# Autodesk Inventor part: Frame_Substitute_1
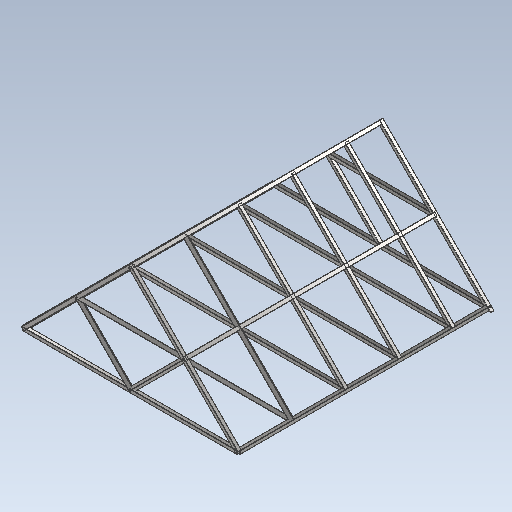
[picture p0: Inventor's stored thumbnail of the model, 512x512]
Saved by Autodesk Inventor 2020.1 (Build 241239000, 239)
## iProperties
Created: 2019-10
Part Number: Frame_Substitute_1
Material: Generic
Document SubType Name: Modeling
Designer: Synergysoft Dell02
Density: 1 g/cm^3
Appearance: Default
Author: Synergysoft Dell02
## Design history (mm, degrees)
derived "Frame.iam"
body "Solid1"
node "Frame 1572343187933.iam:1::ISO 100x100x4:1"
node "Frame 1572343187933.iam:1::ISO 100x100x4:2"
body "Solid2"
node "Frame 1572343187933.iam:1::ISO 100x100x4:3"
body "Solid3"
node "Frame 1572343187933.iam:1::ISO 100x100x4:4"
body "Solid4"
node "Frame 1572343187933.iam:1::ISO 100x100x4:5"
body "Solid5"
node "Frame 1572343187933.iam:1::ISO 100x100x4:6"
body "Solid6"
node "Frame 1572343187933.iam:1::ISO 100x100x4:7"
body "Solid7"
node "Frame 1572343187933.iam:1::ISO 100x100x4:8"
body "Solid8"
node "Frame 1572343187933.iam:1::ISO 100x100x4:9"
body "Solid9"
node "Frame 1572343187933.iam:1::ISO 100x100x4:10"
body "Solid10"
node "Frame 1572343187933.iam:1::ISO 100x100x4:11"
body "Solid11"
node "Frame 1572343187933.iam:1::ISO 100x100x4:12"
body "Solid12"
node "Frame 1572343187933.iam:1::ISO 100x100x4:13"
body "Solid13"
node "Frame 1572343187933.iam:1::ISO 100x100x4:14"
body "Solid14"
node "Frame 1572343187933.iam:1::ISO 100x100x4:15"
body "Solid15"
node "Frame 1572343187933.iam:1::ISO 100x100x4:16"
body "Solid16"
node "Frame 1572343187933.iam:1::ISO 100x100x4:17"
body "Solid17"
node "Frame 1572343187933.iam:1::ISO 100x100x4:18"
body "Solid18"
node "Frame 1572343187933.iam:1::ISO 100x100x4:19"
body "Solid19"
node "Frame 1572343187933.iam:1::ISO 100x100x4:20"
body "Solid20"
node "Frame 1572343187933.iam:1::ISO 100x100x4:21"
body "Solid21"
node "Frame 1572343187933.iam:1::ISO 100x100x4:22"
body "Solid22"
node "Frame 1572343187933.iam:1::ISO 100x100x4:23"
body "Solid23"
node "Frame 1572343187933.iam:1::ISO 100x100x4:24"
body "Solid24"
node "Frame 1572343187933.iam:1::ISO 100x100x4:25"
body "Solid25"
node "Frame 1572343187933.iam:1::ISO 100x100x4:26"
body "Solid26"
node "Frame 1572343187933.iam:1::ISO 100x100x4:27"
body "Solid27"
node "Frame 1572343187933.iam:1::ISO 100x100x4:28"
body "Solid28"
node "Frame 1572343187933.iam:1::ISO 100x100x4:29"
body "Solid29"
